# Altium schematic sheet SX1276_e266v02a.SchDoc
size A3
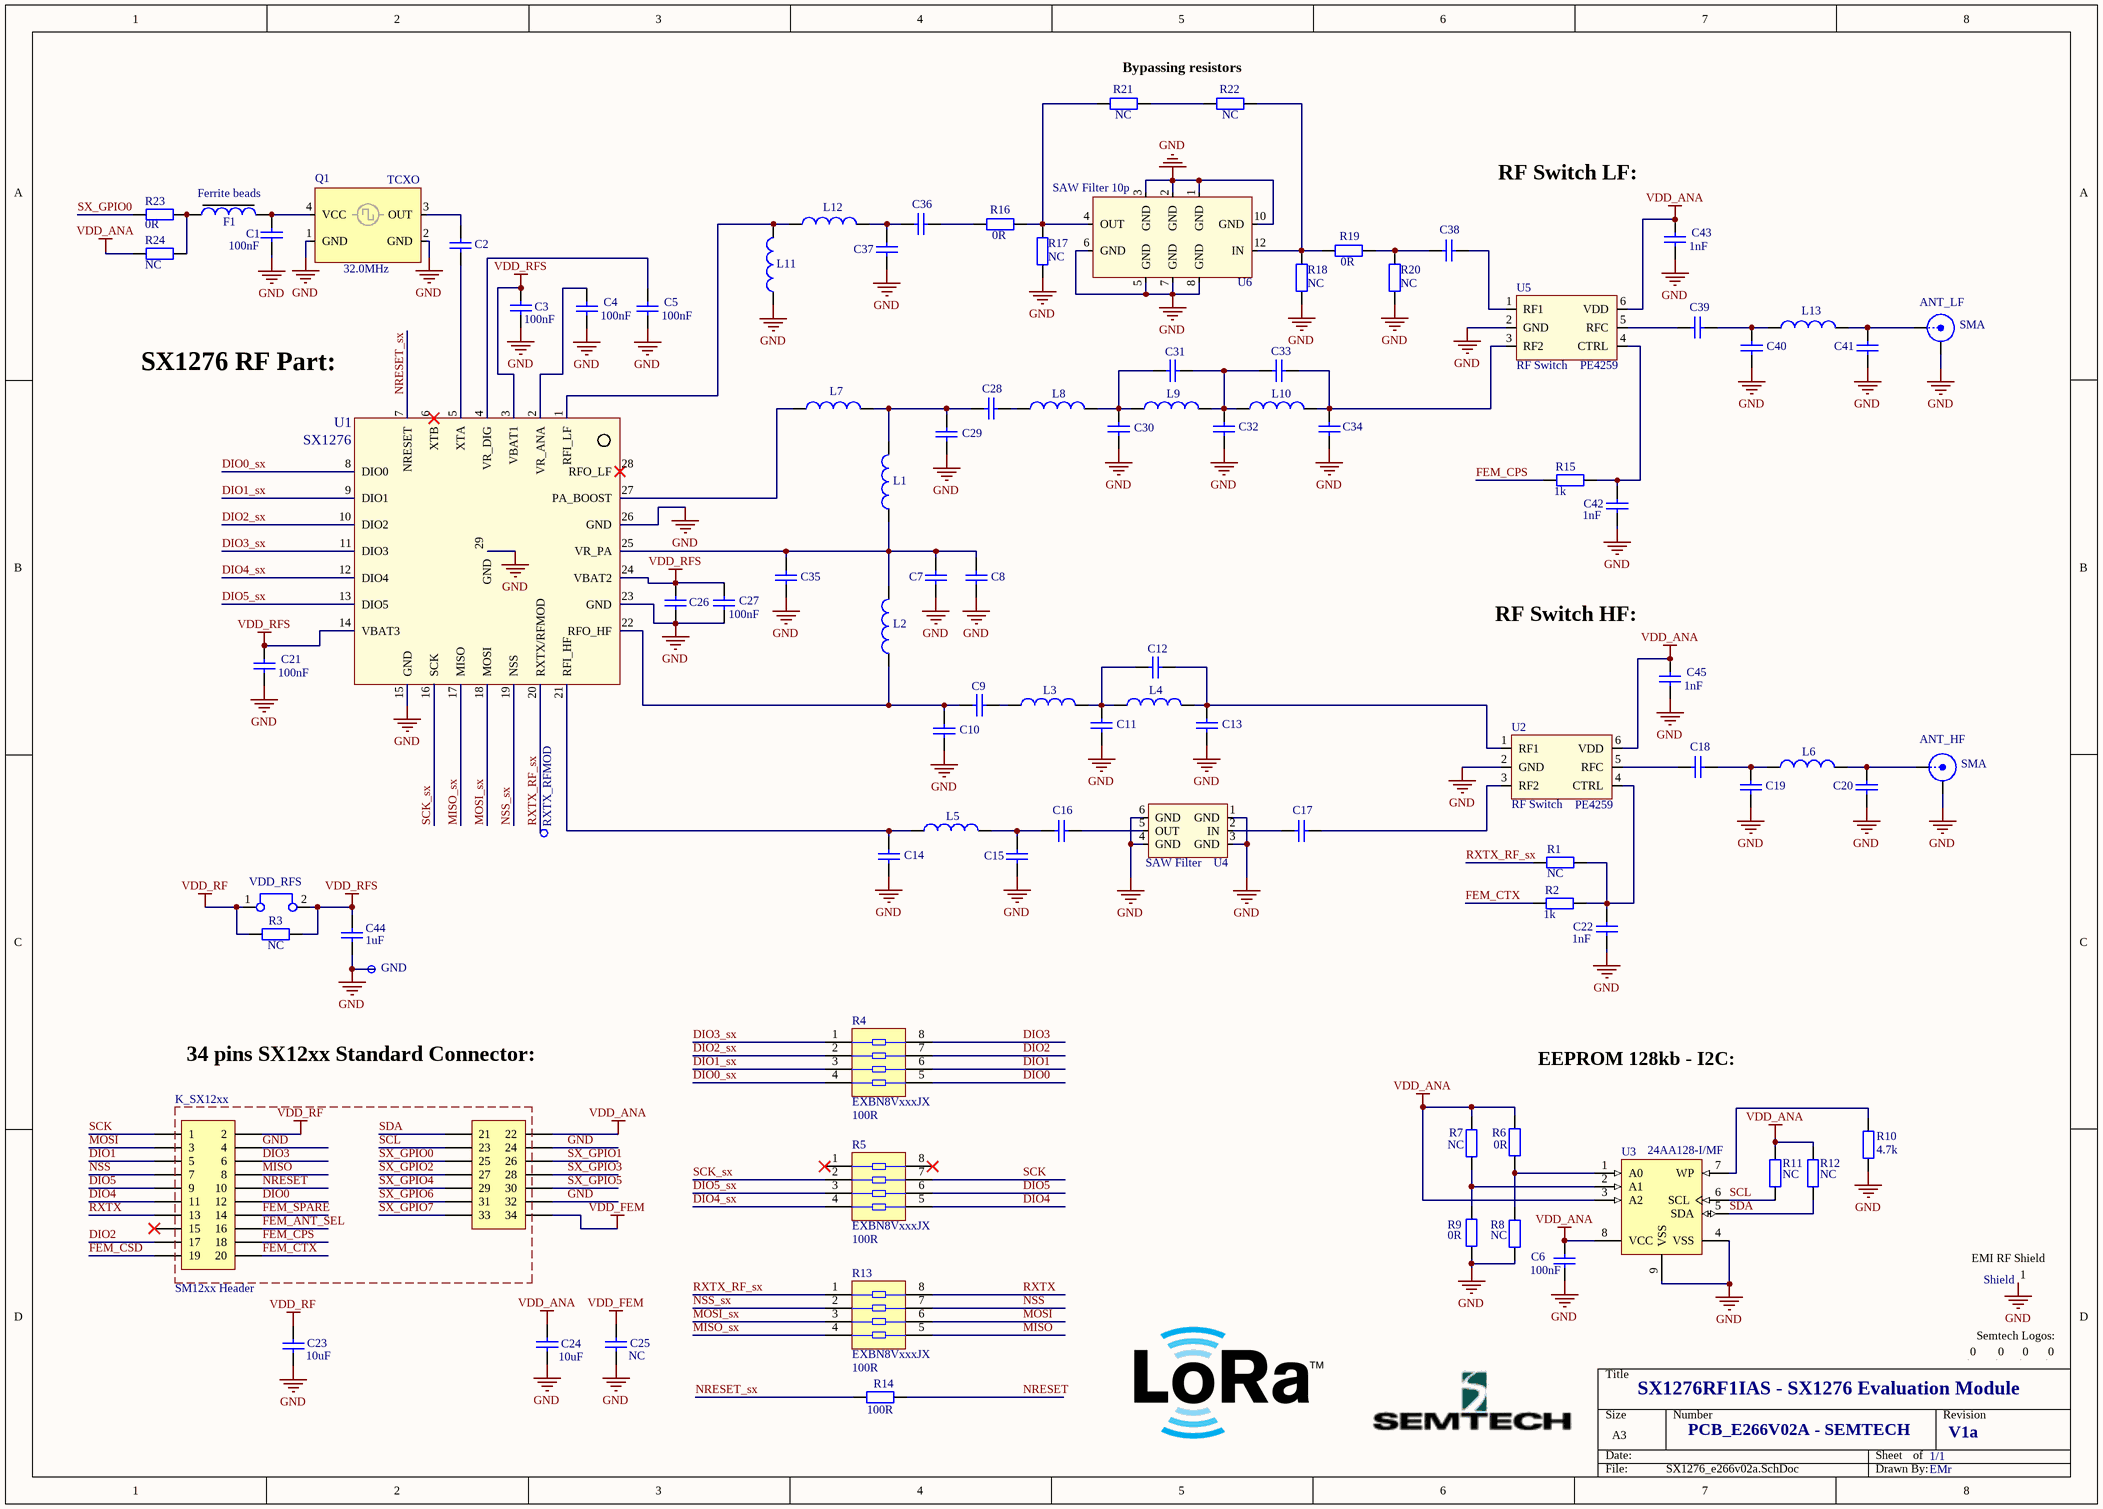
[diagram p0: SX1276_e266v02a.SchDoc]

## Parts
ANT_HF  SMA  [SMA END LAUNCH JACK RECEPTACLE SHORT]
ANT_LF  SMA  [SMA END LAUNCH JACK RECEPTACLE SHORT]
C1  value 100nF  [rlc_402_smd]  (hidden comment: Cap)
C2  Cap  [rlc_402_smd]  (value not drawn)
C3  value 100nF  [rlc_402_smd]  (hidden comment: Cap)
C4  value 100nF  [rlc_402_smd]  (hidden comment: Cap)
C5  value 100nF  [rlc_402_smd]  (hidden comment: Cap)
C6  value 100nF  [rlc_402_smd]  (hidden comment: Cap)
C7  Cap  [rlc_402_smd]  (value not drawn)
C8  Cap  [rlc_402_smd]  (value not drawn)
C9  Cap  [rlc_402_smd]  (value not drawn)
C10  Cap  [rlc_402_smd]  (value not drawn)
C11  Cap  [rlc_402_smd]  (value not drawn)
C12  Cap  [rlc_402_smd]  (value not drawn)
C13  Cap  [rlc_402_smd]  (value not drawn)
C14  Cap  [rlc_402_smd]  (value not drawn)
C15  Cap  [rlc_402_smd]  (value not drawn)
C16  Cap  [rlc_402_smd]  (value not drawn)
C17  Cap  [rlc_402_smd]  (value not drawn)
C18  Cap  [rlc_402_smd]  (value not drawn)
C19  Cap  [rlc_402_smd]  (value not drawn)
C20  Cap  [rlc_402_smd]  (value not drawn)
C21  value 100nF  [rlc_402_smd]  (hidden comment: Cap)
C22  value 1nF  [rlc_402_smd]  (hidden comment: Cap)
C23  value 10uF  [rlc_805_smd]  (hidden comment: Cap)
C24  value 10uF  [rlc_805_smd]  (hidden comment: Cap)
C25  value NC  [rlc_805_smd]  (hidden comment: Cap)
C26  Cap  [rlc_402_smd]  (value not drawn)
C27  value 100nF  [rlc_402_smd]  (hidden comment: Cap)
C28  Cap  [rlc_402_smd]  (value not drawn)
C29  Cap  [rlc_402_smd]  (value not drawn)
C30  Cap  [rlc_402_smd]  (value not drawn)
C31  Cap  [rlc_402_smd]  (value not drawn)
C32  Cap  [rlc_402_smd]  (value not drawn)
C33  Cap  [rlc_402_smd]  (value not drawn)
C34  Cap  [rlc_402_smd]  (value not drawn)
C35  Cap  [rlc_402_smd]  (value not drawn)
C36  Cap  [rlc_402_smd]  (value not drawn)
C37  Cap  [rlc_402_smd]  (value not drawn)
C38  Cap  [rlc_402_smd]  (value not drawn)
C39  Cap  [rlc_402_smd]  (value not drawn)
C40  Cap  [rlc_402_smd]  (value not drawn)
C41  Cap  [rlc_402_smd]  (value not drawn)
C42  value 1nF  [rlc_402_smd]  (hidden comment: Cap)
C43  value 1nF  [rlc_402_smd]  (hidden comment: Cap)
C44  value 1uF  [rlc_603_smd]  (hidden comment: Cap Semi)
C45  value 1nF  [rlc_402_smd]  (hidden comment: Cap)
F1  Ferrite beads  [rlc_402_smd]
GND  Test Pin  [pin_1mm]  (value not drawn)
K_SX12xx  SM12xx Header  [HDR34 Header]
L1  Inductor  [rlc_402_smd]  (value not drawn)
L2  Inductor  [rlc_402_smd]  (value not drawn)
L3  Inductor  [rlc_402_smd]  (value not drawn)
L4  Inductor  [rlc_402_smd]  (value not drawn)
L5  Inductor  [rlc_402_smd]  (value not drawn)
L6  Inductor  [rlc_402_smd]  (value not drawn)
L7  Inductor  [rlc_402_smd]  (value not drawn)
L8  Inductor  [rlc_402_smd]  (value not drawn)
L9  Inductor  [rlc_402_smd]  (value not drawn)
L10  Inductor  [rlc_402_smd]  (value not drawn)
L11  Inductor  [rlc_402_smd]  (value not drawn)
L12  Inductor  [rlc_402_smd]  (value not drawn)
L13  Inductor  [rlc_402_smd]  (value not drawn)
Logo_Bot  Logo symbol  [logo_semtech_horiz_size3]  (value not drawn)
Logo_Lora_Bot  Logo symbol  [Logo LoRa Size4]  (value not drawn)
Logo_Lora_Top  Logo symbol  [Logo LoRa Size3]  (value not drawn)
Logo_Top  Logo symbol  [logo_semtech_horiz_size2]  (value not drawn)
Q1  TCXO  value 32.0MHz  [IT3200C TCXO]
R1  value NC  [rlc_402_smd]  (hidden comment: Resistor)
R2  value 1k  [rlc_402_smd]  (hidden comment: Resistor)
R3  value NC  [rlc_805_smd]  (hidden comment: Resistor)
R4  EXBN8VxxxJX  value 100R  [EXB28V]
R5  EXBN8VxxxJX  value 100R  [EXB28V]
R6  value 0R  [rlc_402_smd]  (hidden comment: Resistor)
R7  value NC  [rlc_402_smd]  (hidden comment: Resistor)
R8  value NC  [rlc_402_smd]  (hidden comment: Resistor)
R9  value 0R  [rlc_402_smd]  (hidden comment: Resistor)
R10  value 4.7k  [rlc_402_smd]  (hidden comment: Resistor)
R11  value NC  [rlc_402_smd]  (hidden comment: Resistor)
R12  value NC  [rlc_402_smd]  (hidden comment: Resistor)
R13  EXBN8VxxxJX  value 100R  [EXB28V]
R14  value 100R  [rlc_402_smd]  (hidden comment: Resistor)
R15  value 1k  [rlc_402_smd]  (hidden comment: Resistor)
R16  value 0R  [rlc_402_smd]  (hidden comment: Resistor)
R17  value NC  [rlc_402_smd]  (hidden comment: Resistor)
R18  value NC  [rlc_402_smd]  (hidden comment: Resistor)
R19  value 0R  [rlc_402_smd]  (hidden comment: Resistor)
R20  value NC  [rlc_402_smd]  (hidden comment: Resistor)
R21  value NC  [rlc_402_smd]  (hidden comment: Resistor)
R22  value NC  [rlc_402_smd]  (hidden comment: Resistor)
R23  value 0R  [rlc_402_smd]  (hidden comment: Resistor)
R24  value NC  [rlc_402_smd]  (hidden comment: Resistor)
RXTX_RFMOD  Test Pin  [pin_SMD]  (value not drawn)
Shield  Logo symbol  [BMIS-205-F - Shield]  (value not drawn)
U1  SX1276  [vqfn28_6x6mm]
U2  RF Switch  value PE4259  [SC70-6]
U3  24AA128-I/MF  [DFN8_ 5x6mm]
U4  SAW Filter  [DCC6C_3.0x3.0mm]
U5  RF Switch  value PE4259  [SC70-6]
U6  SAW Filter 10p  [7.0x5.0mm SMD package]
VDD_RFS  Jumper  [bridge_254mm]  (value not drawn)

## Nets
GND: ANT_HF.2(GND) ANT_LF.2(GND) C1.1 C3.1 C4.1 C5.1 C6.1 C7.1 C8.1 C10.1 C11.1 C13.1 C14.1 C15.1 C19.1 C20.1 C21.1 C22.2 C23.1 C24.1 C25.2 C26.1 C27.1 C29.1 C30.1 C32.1 C34.1 C35.1 C37.1 C40.1 C41.1 C42.2 C43.1 C44.1 C45.1 GND.1(pin) K_SX12xx.4 K_SX12xx.24 K_SX12xx.32 L11.1 Q1.1(GND) Q1.2(GND) R8.1 R9.1 R10.1 R17.2 R18.2 R20.2 Shield.1 U1.15(GND) U1.23(GND) U1.26(GND) U1.29(GND) U2.2(GND) U3.4(VSS) U3.9(VSS) U4.1(GND) U4.3(GND) U4.4(GND) U4.6(GND) U5.2(GND) U6.1(GND) U6.2(GND) U6.3(GND) U6.5(GND) U6.6(GND) U6.7(GND) U6.8(GND) U6.10(GND)
VDD_ANA: C6.2 C24.2 C43.2 C45.2 K_SX12xx.22 R6.2 R7.2 R11.2 R12.2 R24.2 U2.6(VDD) U3.3(A2) U3.8(VCC) U5.6(VDD)
VDD_FEM: C25.1 K_SX12xx.34
VDD_RF: C23.2 K_SX12xx.2 R3.2 VDD_RFS.1
VDD_RFS: C3.2 C21.2 C26.2 C27.2 C44.2 R3.1 U1.3(VBAT1) U1.14(VBAT3) U1.24(VBAT2) VDD_RFS.2
DIO0: K_SX12xx.12 R4.5
DIO0_sx: R4.4 U1.8(DIO0)
DIO1: K_SX12xx.5 R4.6
DIO1_sx: R4.3 U1.9(DIO1)
DIO2: K_SX12xx.17 R4.7
DIO2_sx: R4.2 U1.10(DIO2)
DIO3: K_SX12xx.6 R4.8
DIO3_sx: R4.1 U1.11(DIO3)
DIO4: K_SX12xx.11 R5.5
DIO4_sx: R5.4 U1.12(DIO4)
DIO5: K_SX12xx.9 R5.6
DIO5_sx: R5.3 U1.13(DIO5)
FEM_ANT_SEL: K_SX12xx.16
FEM_CPS: K_SX12xx.18 R15.2
FEM_CSD: K_SX12xx.19
FEM_CTX: K_SX12xx.20 R2.2
FEM_SPARE: K_SX12xx.14
MISO: K_SX12xx.8 R13.5
MISO_sx: R13.4 U1.17(MISO)
MOSI: K_SX12xx.3 R13.6
MOSI_sx: R13.3 U1.18(MOSI)
NRESET: K_SX12xx.10 R14.2
NRESET_sx: R14.1 U1.7(NRESET)
NSS: K_SX12xx.7 R13.7
NSS_sx: R13.2 U1.19(NSS)
RXTX: K_SX12xx.13 R13.8
RXTX_RF_sx: R1.1 R13.1 RXTX_RFMOD.1(pin) U1.20(RXTX/RFMOD)
SCK: K_SX12xx.1 R5.7
SCK_sx: R5.2 U1.16(SCK)
SCL: K_SX12xx.23 R11.1 U3.6(SCL)
SDA: K_SX12xx.21 R12.1 U3.5(SDA)
SX_GPIO0: K_SX12xx.25 R23.1
SX_GPIO1: K_SX12xx.26
SX_GPIO2: K_SX12xx.27
SX_GPIO3: K_SX12xx.28
SX_GPIO4: K_SX12xx.29
SX_GPIO5: K_SX12xx.30
SX_GPIO6: K_SX12xx.31
SX_GPIO7: K_SX12xx.33
NetANT_HF_1: ANT_HF.1(Signal) C20.2 L6.2
NetANT_LF_1: ANT_LF.1(Signal) C41.2 L13.2
NetC1_2: C1.2 F1.2 Q1.4(VCC)
NetC2_1: C2.1 Q1.3(OUT)
NetC2_2: C2.2 U1.5(XTA)
NetC4_2: C4.2 U1.2(VR_ANA)
NetC5_2: C5.2 U1.4(VR_DIG)
NetC7_2: C7.2 C8.2 C35.2 L1.1 L2.2 U1.25(VR_PA)
NetC9_1: C9.1 L3.1
NetC9_2: C9.2 C10.2 L2.1 U1.22(RFO_HF)
NetC11_2: C11.2 C12.2 L3.2 L4.1
NetC12_1: C12.1 C13.2 L4.2 U2.1(RF1)
NetC14_2: C14.2 L5.1 U1.21(RFI_HF)
NetC15_2: C15.2 C16.2 L5.2
NetC16_1: C16.1 U4.5(OUT)
NetC17_1: C17.1 U2.3(RF2)
NetC17_2: C17.2 U4.2(IN)
NetC18_1: C18.1 C19.2 L6.1
NetC18_2: C18.2 U2.5(RFC)
NetC22_1: C22.1 R1.2 R2.1 U2.4(CTRL)
NetC28_1: C28.1 L8.1
NetC28_2: C28.2 C29.2 L1.2 L7.2
NetC30_2: C30.2 C31.2 L8.2 L9.1
NetC31_1: C31.1 C32.2 C33.2 L9.2 L10.1
NetC33_1: C33.1 C34.2 L10.2 U5.3(RF2)
NetC36_1: C36.1 R16.2
NetC36_2: C36.2 C37.2 L12.2
NetC38_1: C38.1 U5.1(RF1)
NetC38_2: C38.2 R19.1 R20.1
NetC39_1: C39.1 C40.2 L13.1
NetC39_2: C39.2 U5.5(RFC)
NetC42_1: C42.1 R15.1 U5.4(CTRL)
NetF1_1: F1.1 R23.2 R24.1
NetL7_1: L7.1 U1.27(PA_BOOST)
NetL11_2: L11.2 L12.1 U1.1(RFI_LF)
NetR6_1: R6.1 R8.2 U3.1(A0)
NetR7_1: R7.1 R9.2 U3.2(A1)
NetR10_2: R10.2 U3.7(WP)
NetR16_1: R16.1 R17.1 R21.2 U6.4(OUT)
NetR18_1: R18.1 R19.2 R22.1 U6.12(IN)
NetR21_1: R21.1 R22.2

Not connected (* = marked no-connect by the designer): K_SX12xx 15*; Logo_Bot 0; Logo_Lora_Bot 0; Logo_Lora_Top 0; Logo_Top 0; R5 1* 8*; U1 6(XTB)* 28(RFO_LF)*

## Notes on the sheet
- Bypassing resistors
- RF Switch LF:
- (near U1) SX1276 RF Part:
- RF Switch HF:
- 34 pins SX12xx Standard Connector:
- EEPROM 128kb - I2C:
- (near Shield) EMI RF Shield
- SX1276RF1IAS - SX1276 Evaluation Module
- Semtech Logos:
- PCB_E266V02A - SEMTECH
- 1/1
- V1a
- EMr

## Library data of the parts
ANT_HF ANT_LF = SMA: SMA Straight Connector
C1 C3-C6 C21-C25 C27 C42 C43 C45 = Cap: Capacitor SMD
C2 C7-C18 C28-C33 C35-C39 = Cap: Capacitor SMD; Value: 100nF
C19 C20 C34 C40 C41 = Cap: Capacitor SMD; Value: NC
C26 = Cap: Capacitor SMD; Value: 100pF
C44 = Cap Semi: Capacitor (Semiconductor SIM Model)
F1 = Ferrite beads: Value: VAL?
GND RXTX_RFMOD = test_pin
K_SX12xx = SM12xx Header: SM12xx Header; 34pins: 2x10pins + 2x7pins
L1-L5 L7-L9 L12 = Inductor: Inductor SMD; Code_IEC: 1005; Value: VAL?
L6 L10 L11 L13 = Inductor: Inductor SMD; Code_IEC: 1005; Value: 0R
Logo_Bot Logo_Lora_Bot Logo_Lora_Top Logo_Top = Logo: Schematic symbol for Logo
R1-R3 R6-R12 R14-R24 = Resistor: Resistor SMD - IEC symbol version
R4 R5 R13 = EXBN8VxxxJX: Mini-Flat Package, Isolated Resistor Network, 0.031 W/resistor
Shield = Shield: Shield - EMI Gasket - Standard Surface Mount Shields
U1 = SX1276: SX1276 - Low Power Integrated UHF Transceiver with loRa Modem
U2 U5 = PE4259 RF Switch: PE4259 Peregrine RF Switch
U3 = 24AA128-I/MF: 128kbit, 400kHz, 1.7V, 8-Pin DFN, Industrial Temperature
U4 = SAW Filter: SAW Filter - Bandpass - TEMEX type
U6 = SAW Filter 10p: SAW Filter 10p  - Bandpass - RFM type
VDD_RFS = Jumper: Jumper Wire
